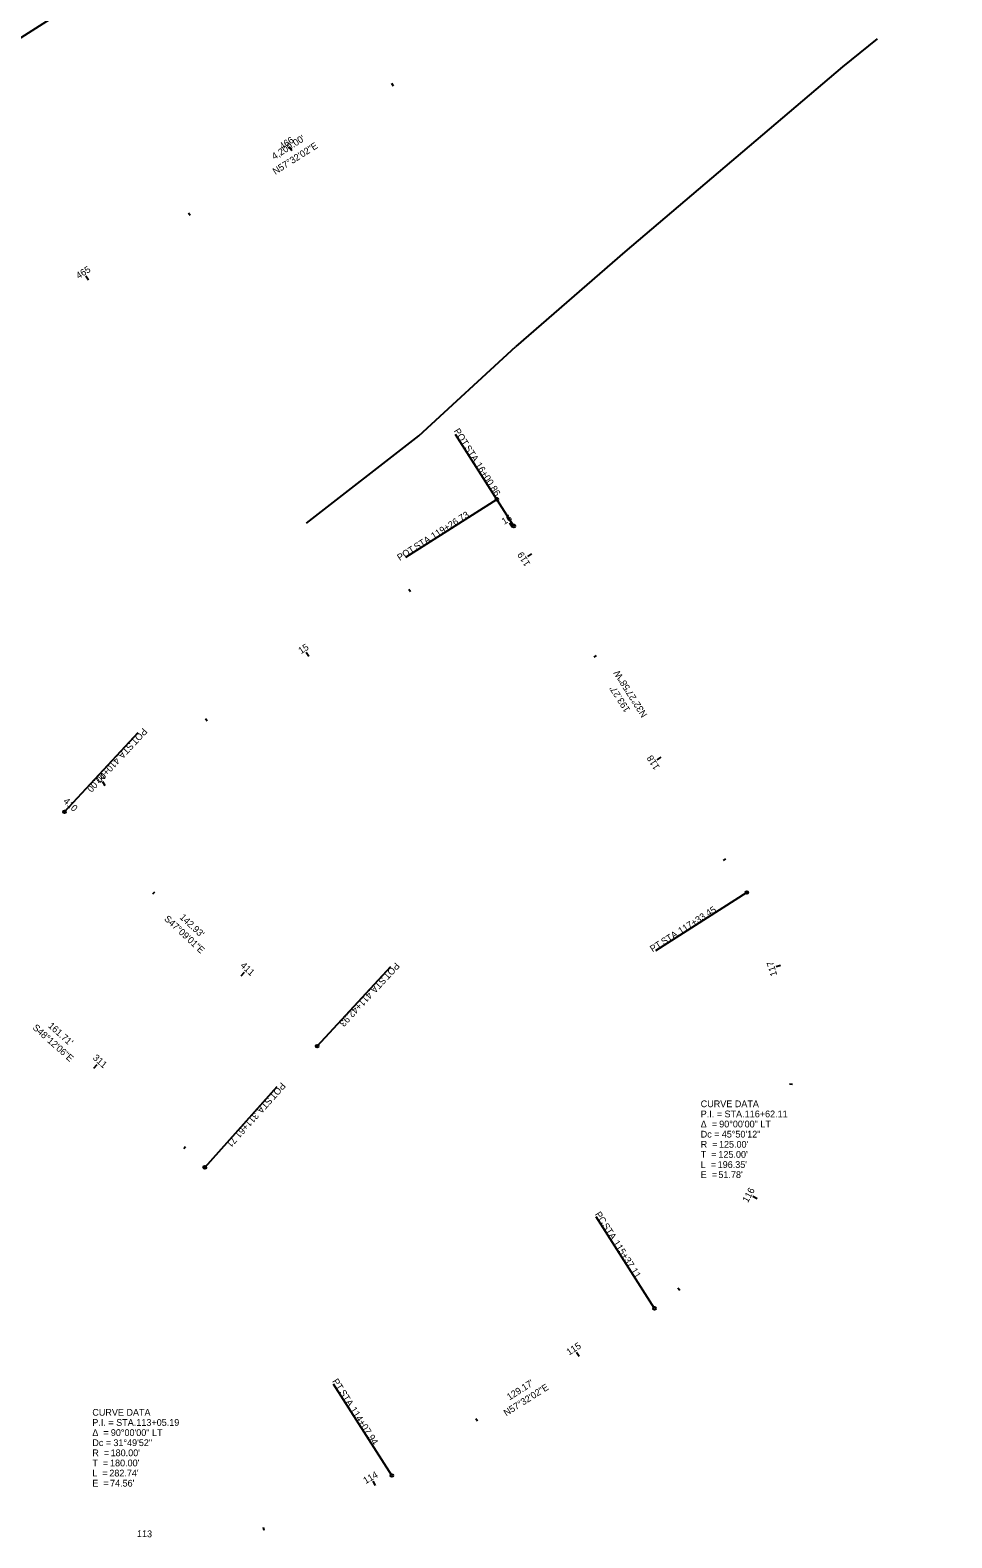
# Model space of a CAD drawing. Extents: x 143421 to 147121, y 511505 to 514560.
# Drawn here: x 145137 to 145520, y 512816 to 513442 of the extents above; entities that cross this region are included whole.
import ezdxf

# ---------------------------------------------------------------- set-up
doc = ezdxf.new("R2010")
doc.units = 0
for name, color, linetype in [('CM_Corridor_Top_Mesh', 7, 'Continuous'), ('DR_Pond', 7, 'Continuous'), ('DT_P_Tie', 7, 'Continuous'), ('DT_X_Contour_Major', 7, 'Continuous'), ('DT_X_Contour_Minor', 7, 'Continuous'), ('DT_X_Spot_Elev', 7, 'Continuous'), ('DT_X_Triangles', 7, 'Continuous'), ('DT_X_Void', 7, 'Continuous'), ('MD_P_Surface_Finished_Grade', 7, 'Continuous'), ('PF_X_Ground_Line', 7, 'Continuous')]:
    doc.layers.add(name, color=color, linetype=linetype)

msp = doc.modelspace()

# ---------------------------------------------------------------- linework, layer by layer
at = {"layer": 'DR_Pond'}
msp.add_lwpolyline([(144475.14, 513019.58), (145011.95, 512175.87), (145117.41, 512242.97), (145222.87, 512310.07), (145328.34, 512377.17), (145433.8, 512444.27), (145539.26, 512511.37), (145644.73, 512578.47), (145750.19, 512645.57), (145855.65, 512712.67), (145961.12, 512779.77), (146066.58, 512846.87), (145529.78, 513690.58), (145424.32, 513623.48), (145318.85, 513556.38), (145213.39, 513489.28), (145107.93, 513422.18), (145002.46, 513355.08), (144897, 513287.98), (144791.53, 513220.88), (144686.07, 513153.78), (144580.61, 513086.68)], close=True, dxfattribs=at)
at = {"layer": 'DT_P_Tie'}
for p, q in [((145338.11, 513235.81), (145313.96, 513273.78)), ((145331.09, 513246.84), (145293.13, 513222.69)), ((145151.72, 513117.22), (145182.33, 513150.21)), ((145434.84, 513083.78), (145396.87, 513059.62)), ((145256.51, 513020.01), (145287.12, 513053)), ((145209.88, 512969.74), (145239.88, 513003.29)), ((145396.48, 512911.21), (145372.32, 512949.18)), ((145287.5, 512841.88), (145263.34, 512879.84))]:
    msp.add_line(p, q, dxfattribs=at)
for centre in [(145331.09, 513246.84), (145338.11, 513235.81), (145151.72, 513117.22), (145434.84, 513083.78), (145256.51, 513020.01), (145209.88, 512969.74), (145396.48, 512911.21), (145287.5, 512841.88)]:
    msp.add_circle(centre, 0.6, dxfattribs=at)
at = {"layer": 'DT_X_Contour_Major'}
for p, q in [((145288.16, 513418.33), (145287.52, 513419.34)), ((145245.98, 513391.49), (145244.9, 513393.17)), ((145203.79, 513364.65), (145203.15, 513365.66)), ((145161.61, 513337.81), (145160.53, 513339.49))]:
    msp.add_line(p, q, dxfattribs=at)
at = {"layer": 'DT_X_Triangles'}
for p, q in [((145337.38, 513235.34), (145336.31, 513237.03)), ((145345.44, 513224.29), (145343.75, 513223.22)), ((145295.2, 513208.5), (145294.55, 513209.52)), ((145253.01, 513181.66), (145251.94, 513183.35)), ((145372.28, 513182.11), (145371.27, 513181.46)), ((145210.83, 513154.82), (145210.18, 513155.84)), ((145399.12, 513139.92), (145397.43, 513138.85)), ((145168.64, 513127.98), (145167.57, 513129.67)), ((145151.72, 513117.22), (145153.08, 513118.69)), ((145425.96, 513097.74), (145424.95, 513097.09)), ((145188.38, 513083.22), (145189.2, 513084.1)), ((145225.04, 513049.21), (145226.4, 513050.68)), ((145448.83, 513053.5), (145446.92, 513052.91)), ((145163.88, 513010.87), (145165.21, 513012.36)), ((145453.74, 513004.07), (145452.55, 513004.19)), ((145201.16, 512977.55), (145201.96, 512978.44)), ((145439.02, 512956.64), (145437.26, 512957.6)), ((145406.98, 512918.68), (145406.24, 512919.62)), ((145365.17, 512891.3), (145364.1, 512892.98)), ((145322.99, 512864.46), (145322.34, 512865.47)), ((145280.71, 512837.76), (145279.71, 512839.5)), ((145234.49, 512819.11), (145234.2, 512820.27))]:
    msp.add_line(p, q, dxfattribs=at)
at = {"layer": 'DT_X_Void'}
for points in [[(145488.9, 513437.9), (145474.43, 513426.25), (145384.25, 513349.62), (145338.93, 513310.27)], [(145252.06, 513236.96), (145298.7, 513273.21), (145338.93, 513310.27)]]:
    msp.add_lwpolyline(points, dxfattribs=at)

# ---------------------------------------------------------------- texts
at = {"layer": 'CM_Corridor_Top_Mesh'}
for s, rotation, p in [("193.27'", 122.46616, (145386.52, 513159.65)), ("142.93'", 317.15037, (145199.25, 513073.19)), ("161.71'", 318.20179, (145144.66, 513028.12)), ("129.17'", 32.46616, (145336.33, 512872.99))]:
    msp.add_text(s, height=2.8, rotation=rotation, dxfattribs=at).set_placement(p)
at = {"layer": 'DT_P_Tie'}
for s, rotation, p in [('POT', 302.46616, (145313.08, 513275.23)), (' STA. ', 302.46616, (145316.95, 513269.15)), ('16+00.86', 302.46616, (145322.02, 513261.18)), ('119+26.73', 32.46616, (145304.85, 513230.2)), (' STA. ', 32.46616, (145296.88, 513225.13)), ('POT', 32.46616, (145290.8, 513221.26)), ('POT', 227.15037, (145184.26, 513152.23)), (' STA. ', 227.15037, (145179.36, 513146.96)), ('410+00.00', 227.15037, (145172.94, 513140.03)), ('117+33.45', 32.46616, (145407.4, 513066.37)), ('PT', 32.46616, (145395.7, 513058.92)), (' STA. ', 32.46616, (145399.43, 513061.29)), ('POT', 227.15037, (145289, 513054.97)), (' STA. ', 227.15037, (145284.1, 513049.69)), ('411+42.93', 227.15037, (145277.68, 513042.76)), ('POT', 228.20179, (145241.64, 513005.2)), (' STA. ', 228.20179, (145236.84, 512999.84)), ('311+61.71', 228.20179, (145230.54, 512992.79)), ('PC', 302.46616, (145371.66, 512950.3)), (' STA. ', 302.46616, (145374.12, 512946.43)), ('115+37.11', 302.46616, (145379.2, 512938.45)), ('PT', 302.46616, (145262.66, 512880.99)), (' STA. ', 302.46616, (145265.03, 512877.26)), ('114+07.94', 302.46616, (145270.11, 512869.29))]:
    msp.add_text(s, height=2.8, rotation=rotation, dxfattribs=at).set_placement(p)
at = {"layer": 'DT_X_Contour_Major'}
for s, p in [('466', (145241.89, 513391.85)), ('465', (145157.56, 513338.19))]:
    msp.add_text(s, height=2.8, rotation=32.46616, dxfattribs=at).set_placement(p)
at = {"layer": 'DT_X_Contour_Minor'}
msp.add_text('N57°32\'02"E', height=2.8, rotation=32.46616, dxfattribs=at).set_placement((145239.17, 513381.47))
at = {"layer": 'DT_X_Spot_Elev'}
msp.add_text("4,200.00'", height=2.8, rotation=32.46616, dxfattribs=at).set_placement((145238.81, 513387.67))
at = {"layer": 'DT_X_Triangles'}
for s, rotation, p in [('16', 32.46616, (145334.15, 513236.25)), ('119', 122.46616, (145345.11, 513220.15)), ('15', 32.46616, (145249.82, 513182.6)), ('118', 122.46616, (145398.8, 513135.77)), ('14', 32.46616, (145165.48, 513128.94)), ('410', 317.15037, (145150.97, 513121.33)), ('411', 317.15037, (145224.43, 513053.19)), ('117', 107.13154, (145447.45, 513049.5)), ('311', 318.20179, (145163.2, 513014.84)), ('116', 61.29491, (145435.21, 512954.89)), ('115', 32.46616, (145361.04, 512891.63)), ('114', 29.93972, (145276.63, 512838.3)), ('113', 358.10873, (145181.74, 512816.45))]:
    msp.add_text(s, height=2.8, rotation=rotation, dxfattribs=at).set_placement(p)
at = {"layer": 'MD_P_Surface_Finished_Grade'}
for s, p in [('CURVE DATA', (145415.66, 512994.7)), ('P.I. = STA. ', (145415.66, 512990.5)), ('116+62.11', (145433.93, 512990.5)), ('Δ  = ', (145415.66, 512986.3)), ('90°00\'00" LT', (145423.34, 512986.3)), ('Dc = ', (145415.66, 512982.1)), ('45°50\'12"', (145424.4, 512982.1)), ('T  = ', (145415.66, 512973.7)), ('R  = ', (145415.66, 512977.9)), ("125.00'", (145423, 512973.7)), ("125.00'", (145423.24, 512977.9)), ('L  = ', (145415.66, 512969.5)), ("196.35'", (145422.7, 512969.5)), ('E  = ', (145415.66, 512965.3)), ("51.78'", (145423, 512965.3)), ('CURVE DATA', (145163.25, 512866.7)), ('P.I. = STA. ', (145163.25, 512862.5)), ('113+05.19', (145181.52, 512862.5)), ('Δ  = ', (145163.25, 512858.3)), ('Dc = ', (145163.25, 512854.1)), ('90°00\'00" LT', (145170.93, 512858.3)), ('31°49\'52"', (145171.99, 512854.1)), ('R  = ', (145163.25, 512849.9)), ("180.00'", (145170.83, 512849.9)), ('T  = ', (145163.25, 512845.7)), ('L  = ', (145163.25, 512841.5)), ("282.74'", (145170.29, 512841.5)), ("180.00'", (145170.59, 512845.7)), ('E  = ', (145163.25, 512837.3)), ("74.56'", (145170.59, 512837.3))]:
    msp.add_text(s, height=2.8, dxfattribs=at).set_placement(p)
at = {"layer": 'PF_X_Ground_Line'}
for s, rotation, p in [('N32°27\'58"W', 122.46616, (145393.63, 513157.5)), ('S47°09\'01"E', 317.15037, (145192.83, 513072.54)), ('S48°12\'06"E', 318.20179, (145138.25, 513027.35)), ('N57°32\'02"E', 32.46616, (145334.98, 512866.4))]:
    msp.add_text(s, height=2.8, rotation=rotation, dxfattribs=at).set_placement(p)

doc.saveas('drawing.dxf')
